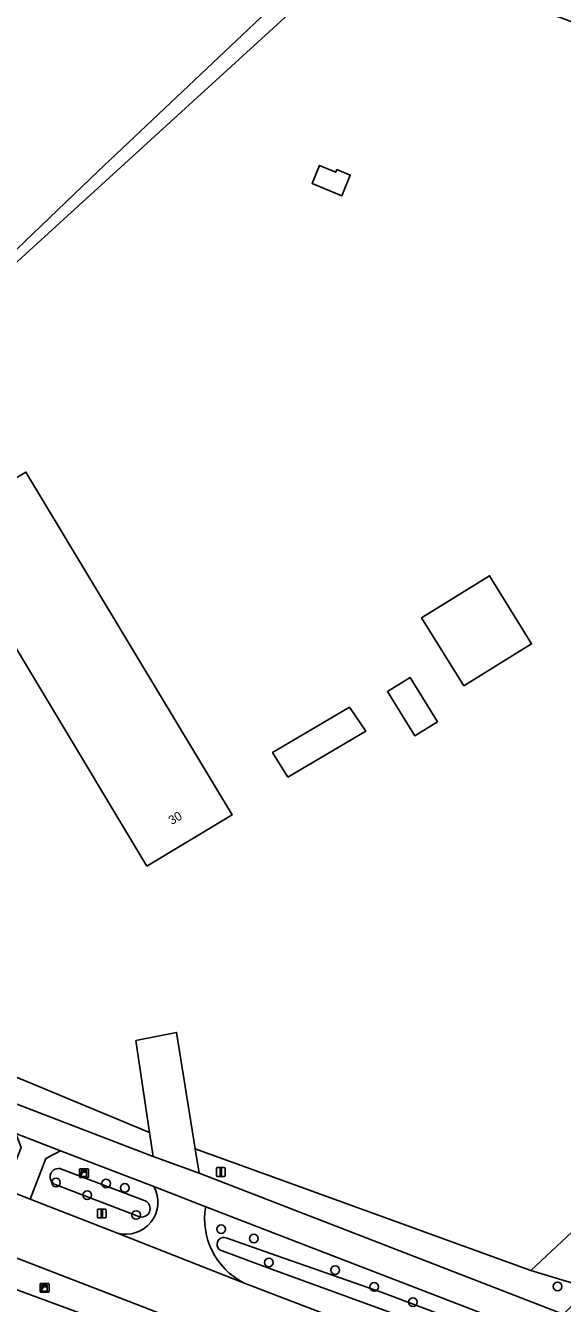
# Model space of a CAD drawing. Extents: x 155209 to 156748, y 385356 to 388487.
# Drawn here: x 155762.9 to 155823.6, y 386710.5 to 386855.1 of the extents above; entities that cross this region are included whole.
import ezdxf

# ---------------------------------------------------------------- set-up
doc = ezdxf.new("R2010")
doc.units = 0
for name, color, linetype in [('IMGEO_Berm_groen', 7, 'Continuous'), ('IMGEO_Boom', 7, 'Continuous'), ('IMGEO_Bouwland', 7, 'Continuous'), ('IMGEO_Erf', 7, 'Continuous'), ('IMGEO_Fietspad_gesloten', 7, 'Continuous'), ('IMGEO_Gemengd_bos', 7, 'Continuous'), ('IMGEO_Hek', 7, 'Continuous'), ('IMGEO_Kast', 7, 'Continuous'), ('IMGEO_Lichtmast', 7, 'Continuous'), ('IMGEO_Pand', 7, 'Continuous'), ('IMGEO_Pand_nummerreeks', 7, 'Continuous'), ('IMGEO_Rijbaan_lokaal_gesloten', 7, 'Continuous'), ('IMGEO_Rijbaan_lokaal_open', 7, 'Continuous'), ('IMGEO_Voetpad_open', 7, 'Continuous'), ('IMGEO_Waterloop', 7, 'Continuous')]:
    doc.layers.add(name, color=color, linetype=linetype)

msp = doc.modelspace()

# ---------------------------------------------------------------- linework, layer by layer
at = {"layer": 'IMGEO_Berm_groen'}
for points in [[(155476.96, 386846.12), (155486.55, 386842.14), (155500, 386836.47), (155529.41, 386824.07), (155542.24, 386818.67), (155597.75, 386796.8), (155650.37, 386775.84), (155664.94, 386770.25), (155717.68, 386750), (155777.32, 386727.1), (155776.91, 386729.81), (155728.33, 386750), (155696.05, 386763.44)], [(155777.37, 386723.68), (155766.81, 386727.74), (155765.18, 386726.86), (155763.39, 386722.27), (155773.27, 386718.42)], [(155766.96, 386725.67), (155776.4, 386722.08)], [(155775.69, 386720.3), (155766.22, 386723.92)], [(155791.39, 386718.27), (155783.26, 386721.41)], [(155785.57, 386717.88), (155790.57, 386716.13), (155803.21, 386711.7), (155818.46, 386705.97), (155817.55, 386704.28), (155803.73, 386709.57), (155789.98, 386714.61), (155785.11, 386716.4)], [(155787.54, 386712.8), (155818.26, 386701.02), (155821.98, 386706.46), (155791.39, 386718.27)], [(155786.7, 386706.02), (155761.51, 386715.74), (155760.31, 386714.85), (155759.25, 386713.89), (155758.81, 386713.23), (155761.07, 386712.32), (155761.11, 386712.3), (155783.77, 386703.93), (155785.63, 386703.2), (155808.7, 386694.05)]]:
    msp.add_lwpolyline(points, dxfattribs=at)
msp.add_lwpolyline([(155793.53, 386723.81), (155782.08, 386727.97), (155782.52, 386725.2), (155792.56, 386721.3), (155823.67, 386709.23), (155826.78, 386712.15), (155820.02, 386714.17)], close=True, dxfattribs=at)
for centre, radius, start, end in [((155766.61, 386724.78), 0.951, 68.5692, 245.6669), ((155774.23, 386721.9), 3.61, 254.598, 29.5253), ((155776.01, 386721.2), 0.958, 250.1617, 66.1132), ((155791.26, 386720.03), 8.13, 170.1841, 242.7489), ((155785.31, 386717.15), 0.776, 71.0764, 254.4358)]:
    msp.add_arc(centre, radius, start, end, dxfattribs=at)
at = {"layer": 'IMGEO_Boom'}
for centre in [(155766.32, 386724.14), (155771.99, 386724.04), (155769.86, 386722.71), (155774.11, 386723.53), (155775.39, 386720.47), (155784.99, 386718.86), (155788.7, 386717.8), (155790.39, 386715.09), (155797.9, 386714.24), (155802.31, 386712.33), (155823.06, 386712.38), (155806.7, 386710.61)]:
    msp.add_circle(centre, 0.489, dxfattribs=at)
at = {"layer": 'IMGEO_Bouwland'}
msp.add_lwpolyline([(155501.63, 386865.96), (155619.3, 386817.16), (155711.43, 386781.69), (155736.11, 386805.05), (155771.1, 386838.59), (155794.24, 386860.52)], dxfattribs=at)
at = {"layer": 'IMGEO_Erf'}
for points in [[(155895.67, 386784.96), (155927.56, 386817.29), (155801.22, 386864.26), (155757.67, 386824.49), (155759.61, 386822.37), (155696.05, 386763.44), (155728.33, 386750), (155776.91, 386729.81), (155775.36, 386740.2), (155779.95, 386741.14), (155782.08, 386727.97), (155793.53, 386723.81), (155820.02, 386714.17)], [(155795.29, 386837.22), (155796.14, 386839.26), (155797.97, 386838.48), (155798.1, 386838.78), (155799.61, 386838.16), (155798.64, 386835.82)], [(155776.61, 386759.96), (155753.28, 386798.76), (155762.92, 386804.55), (155786.24, 386765.75)], [(155812.44, 386780.35), (155807.67, 386788.05), (155815.36, 386792.81), (155820.12, 386785.1)], [(155809.48, 386776.29), (155806.92, 386774.7), (155803.83, 386779.7), (155806.39, 386781.29)], [(155792.55, 386770.03), (155790.81, 386772.82), (155796.59, 386776.21), (155799.51, 386777.93), (155801.35, 386775.21)]]:
    msp.add_lwpolyline(points, close=True, dxfattribs=at)
at = {"layer": 'IMGEO_Fietspad_gesloten'}
for points in [[(155717.68, 386750), (155664.94, 386770.25), (155663.89, 386767.51), (155697.56, 386754.39), (155708.95, 386750), (155761.76, 386729.68), (155766.81, 386727.74), (155777.37, 386723.68), (155783.26, 386721.41), (155791.39, 386718.27), (155821.98, 386706.46), (155822.58, 386706.23), (155872.83, 386686.83), (155877.68, 386684.79), (155916.39, 386670), (155989.46, 386642), (155994.28, 386640.16), (156000, 386637.97), (156052.47, 386617.83), (156121.21, 386591.61), (156131.18, 386587.42), (156137.33, 386584.91), (156141.25, 386583.25)], [(156000, 386641.23), (155995.68, 386642.88), (155990.49, 386644.88), (155878.92, 386687.63), (155874.11, 386689.65), (155823.67, 386709.23), (155792.56, 386721.3), (155782.52, 386725.2), (155777.32, 386727.1), (155717.68, 386750)]]:
    msp.add_lwpolyline(points, dxfattribs=at)
at = {"layer": 'IMGEO_Gemengd_bos'}
msp.add_lwpolyline([(155794.24, 386860.52), (155771.1, 386838.59), (155736.11, 386805.05), (155711.43, 386781.69), (155695.12, 386766.26), (155690.08, 386764.42), (155696.05, 386763.44), (155759.61, 386822.37), (155757.67, 386824.49), (155801.22, 386864.26), (155927.56, 386817.29), (155895.67, 386784.96), (155820.02, 386714.17), (155826.78, 386712.15), (155846.72, 386730.89), (155867.05, 386750), (155901.78, 386782.87), (155947.83, 386828.58), (156000, 386875.43)], dxfattribs=at)
at = {"layer": 'IMGEO_Hek'}
for points in [[(155696.05, 386763.44), (155759.61, 386822.37), (155757.67, 386824.49), (155801.22, 386864.26), (155927.56, 386817.29), (155895.67, 386784.96), (155820.02, 386714.17)], [(155820.02, 386714.17), (155793.53, 386723.81), (155782.08, 386727.97)]]:
    msp.add_lwpolyline(points, dxfattribs=at)
at = {"layer": 'IMGEO_Kast'}
for p, q in [((155768.98, 386724.78), (155768.98, 386725.62)), ((155768.98, 386725.62), (155768.98, 386724.78)), ((155769.06, 386725.71), (155769.9, 386725.71)), ((155769.9, 386725.71), (155769.06, 386725.71)), ((155769.91, 386724.71), (155769.07, 386724.71)), ((155769.07, 386724.71), (155769.91, 386724.71)), ((155769.98, 386725.63), (155769.98, 386724.79)), ((155769.98, 386724.79), (155769.98, 386725.63)), ((155764.6, 386712.72), (155765.45, 386712.72)), ((155765.45, 386712.72), (155764.6, 386712.72)), ((155764.53, 386711.8), (155764.53, 386712.64)), ((155764.53, 386712.64), (155764.53, 386711.8)), ((155765.46, 386711.73), (155764.61, 386711.73)), ((155764.61, 386711.73), (155765.46, 386711.73)), ((155765.53, 386712.65), (155765.53, 386711.81)), ((155765.53, 386711.81), (155765.53, 386712.65))]:
    msp.add_line(p, q, dxfattribs=at)
for points in [[(155769.18, 386725.5), (155769.78, 386725.5), (155769.78, 386725.41), (155769.18, 386725.41), (155769.18, 386725.5)], [(155769.18, 386725.32), (155769.78, 386725.32), (155769.78, 386724.84), (155769.18, 386724.84), (155769.18, 386725.32)], [(155764.73, 386712.52), (155765.33, 386712.52), (155765.33, 386712.43), (155764.73, 386712.43), (155764.73, 386712.52)], [(155764.73, 386712.34), (155765.33, 386712.34), (155765.33, 386711.85), (155764.73, 386711.85), (155764.73, 386712.34)]]:
    msp.add_lwpolyline(points, dxfattribs=at)
for centre in [(155769.26, 386725.17), (155764.81, 386712.19)]:
    msp.add_circle(centre, 0.0377, dxfattribs=at)
for centre, start, end in [((155769.06, 386725.63), 92.4484, 184.2845), ((155769.06, 386725.63), 92.4484, 184.2845), ((155769.06, 386724.79), 182.4484, 274.2845), ((155769.06, 386724.79), 182.4484, 274.2845), ((155769.91, 386725.63), 2.4484, 94.2845), ((155769.91, 386725.63), 2.4484, 94.2845), ((155769.91, 386724.79), 272.4484, 4.2845), ((155769.91, 386724.79), 272.4484, 4.2845), ((155764.61, 386712.65), 92.4484, 184.2845), ((155764.61, 386712.65), 92.4484, 184.2845), ((155765.45, 386712.65), 2.4484, 94.2845), ((155765.45, 386712.65), 2.4484, 94.2845), ((155764.61, 386711.8), 182.4484, 274.2845), ((155764.61, 386711.8), 182.4484, 274.2845), ((155765.45, 386711.8), 272.4484, 4.2845), ((155765.45, 386711.8), 272.4484, 4.2845)]:
    msp.add_arc(centre, 0.0779, start, end, dxfattribs=at)
at = {"layer": 'IMGEO_Lichtmast'}
for p, q in [((155784.47, 386724.93), (155784.47, 386725.73)), ((155784.47, 386725.73), (155784.47, 386724.93)), ((155784.57, 386725.83), (155785.35, 386725.83)), ((155785.35, 386725.83), (155784.57, 386725.83)), ((155785.45, 386725.73), (155785.45, 386724.93)), ((155785.45, 386724.93), (155785.45, 386725.73)), ((155785.35, 386724.83), (155784.57, 386724.83)), ((155784.57, 386724.83), (155785.35, 386724.83)), ((155771, 386720.24), (155771, 386721.04)), ((155771, 386721.04), (155771, 386720.24)), ((155771.1, 386721.14), (155771.89, 386721.14)), ((155771.89, 386721.14), (155771.1, 386721.14)), ((155771.89, 386720.14), (155771.1, 386720.14)), ((155771.1, 386720.14), (155771.89, 386720.14)), ((155771.99, 386721.04), (155771.99, 386720.24)), ((155771.99, 386720.24), (155771.99, 386721.04))]:
    msp.add_line(p, q, dxfattribs=at)
for points in [[(155784.88, 386725.71), (155785.04, 386725.71), (155785.04, 386724.96), (155784.88, 386724.96), (155784.88, 386725.71)], [(155771.42, 386721.02), (155771.57, 386721.02), (155771.57, 386720.27), (155771.42, 386720.27), (155771.42, 386721.02)]]:
    msp.add_lwpolyline(points, dxfattribs=at)
for centre, start, end in [((155784.57, 386725.73), 90, 180), ((155784.57, 386725.73), 90, 180), ((155785.35, 386725.73), 0, 90), ((155785.35, 386725.73), 360, 90), ((155784.57, 386724.93), 180, 270), ((155784.57, 386724.93), 180, 270), ((155785.35, 386724.93), 270, 0), ((155785.35, 386724.93), 270, 0), ((155771.1, 386721.04), 90, 180), ((155771.1, 386721.04), 90, 180), ((155771.1, 386720.24), 180, 270), ((155771.1, 386720.24), 180, 270), ((155771.89, 386721.04), 0, 90), ((155771.89, 386721.04), 360, 90), ((155771.89, 386720.24), 270, 0), ((155771.89, 386720.24), 270, 0)]:
    msp.add_arc(centre, 0.1, start, end, dxfattribs=at)
at = {"layer": 'IMGEO_Pand'}
for points in [[(155798.64, 386835.82), (155799.61, 386838.16), (155798.1, 386838.78), (155797.97, 386838.48), (155796.14, 386839.26), (155795.29, 386837.22)], [(155776.61, 386759.96), (155786.24, 386765.75), (155762.92, 386804.55), (155753.28, 386798.76)], [(155812.44, 386780.35), (155820.12, 386785.1), (155815.36, 386792.81), (155807.67, 386788.05)], [(155803.83, 386779.7), (155806.92, 386774.7), (155809.48, 386776.29), (155806.39, 386781.29)], [(155792.55, 386770.03), (155801.35, 386775.21), (155799.51, 386777.93), (155796.59, 386776.21), (155790.81, 386772.82)]]:
    msp.add_lwpolyline(points, close=True, dxfattribs=at)
at = {"layer": 'IMGEO_Rijbaan_lokaal_gesloten'}
for points in [[(155818.26, 386701.02), (155787.54, 386712.8), (155773.27, 386718.42), (155763.39, 386722.27), (155760.55, 386723.38), (155692.19, 386750), (155670.45, 386758.36), (155668.79, 386759.03), (155666.17, 386752.49), (155670.72, 386750.79), (155672.76, 386750), (155751.68, 386719.53), (155761.51, 386715.74), (155786.7, 386706.02)], [(155783.26, 386721.41), (155777.37, 386723.68)], [(155773.27, 386718.42), (155787.54, 386712.8)]]:
    msp.add_lwpolyline(points, dxfattribs=at)
for centre, radius, start, end in [((155774.23, 386721.9), 3.61, 254.598, 29.5253), ((155791.26, 386720.03), 8.13, 170.1841, 242.7489)]:
    msp.add_arc(centre, radius, start, end, dxfattribs=at)
at = {"layer": 'IMGEO_Rijbaan_lokaal_open'}
msp.add_lwpolyline([(155779.95, 386741.14), (155775.36, 386740.2), (155776.91, 386729.81), (155777.32, 386727.1), (155782.52, 386725.2), (155782.08, 386727.97)], close=True, dxfattribs=at)
at = {"layer": 'IMGEO_Voetpad_open'}
msp.add_lwpolyline([(155760.55, 386723.38), (155763.39, 386722.27), (155765.18, 386726.86), (155766.81, 386727.74), (155761.76, 386729.68), (155762.36, 386728.09)], close=True, dxfattribs=at)
at = {"layer": 'IMGEO_Waterloop'}
for points in [[(155776.4, 386722.08), (155766.96, 386725.67)], [(155766.22, 386723.92), (155775.69, 386720.3)], [(155785.11, 386716.4), (155789.98, 386714.61), (155803.73, 386709.57), (155817.55, 386704.28), (155818.46, 386705.97), (155803.21, 386711.7), (155790.57, 386716.13), (155785.57, 386717.88)], [(155785.63, 386703.2), (155783.77, 386703.93), (155761.11, 386712.3), (155761.07, 386712.32)]]:
    msp.add_lwpolyline(points, dxfattribs=at)
for centre, radius, start, end in [((155766.61, 386724.78), 0.951, 68.5692, 245.6669), ((155776.01, 386721.2), 0.958, 250.1617, 66.1132), ((155785.31, 386717.15), 0.776, 71.0764, 254.4358)]:
    msp.add_arc(centre, radius, start, end, dxfattribs=at)

# ---------------------------------------------------------------- texts
at = {"layer": 'IMGEO_Pand_nummerreeks'}
msp.add_text('30', height=1, rotation=31.0171, dxfattribs=at).set_placement((155779.42, 386764.59))

doc.saveas('drawing.dxf')
